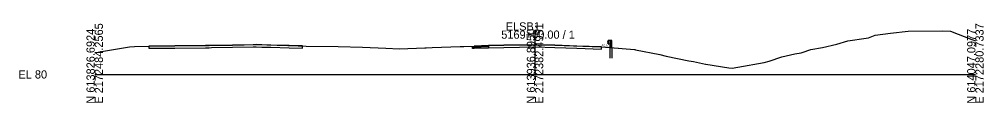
# Model space of a CAD drawing. Extents: x -26 to 1303, y -3010 to 12023.
# Drawn here: x -25.7 to 302.8, y -1509.7 to -1482.2 of the extents above; entities that cross this region are included whole.
import ezdxf

# ---------------------------------------------------------------- set-up
doc = ezdxf.new("R2010")
doc.units = 0
for name, color, linetype in [('RD_GPK_XS_Cell', 7, 'Continuous'), ('RD_PD_Final_TrvlWay', 7, 'Continuous'), ('RD_XS_Base', 7, 'Continuous'), ('RD_XS_ExGround', 7, 'Continuous'), ('RD_XS_ExPaveRet', 7, 'Continuous'), ('RD_XS_GR', 7, 'Continuous'), ('RD_XS_Pave', 7, 'Continuous'), ('RD_XS_PaveOvlay_CP', 7, 'Continuous'), ('RD_XS_TieSlope', 7, 'Continuous'), ('RD_XS_TX_ShdSlope', 7, 'Continuous')]:
    doc.layers.add(name, color=color, linetype=linetype)

msp = doc.modelspace()

# ---------------------------------------------------------------- linework, layer by layer
at = {"layer": 'RD_GPK_XS_Cell'}
for p, q in [((150, -1500), (150, -1485)), ((0, -1500), (150, -1500)), ((150, -1500), (300, -1500))]:
    msp.add_line(p, q, dxfattribs=at)
at = {"layer": 'RD_PD_Final_TrvlWay'}
for p, q in [((175.63, -1494.42), (175.63, -1490.81)), ((175.63, -1490.81), (176.13, -1490.85)), ((176.13, -1490.85), (176.13, -1494.42))]:
    msp.add_line(p, q, dxfattribs=at)
at = {"layer": 'RD_XS_Base'}
for p, q in [((128.72, -1491.15), (128.72, -1491.15)), ((128.72, -1491.15), (128.72, -1491.15)), ((128.73, -1490.65), (129.23, -1490.63)), ((128.73, -1491.15), (128.73, -1490.65)), ((128.73, -1490.65), (128.73, -1490.65)), ((129.22, -1491.13), (128.73, -1491.15)), ((134.17, -1490.98), (129.22, -1491.13)), ((129.22, -1491.13), (129.22, -1491.13)), ((129.23, -1490.63), (134.17, -1490.48)), ((129.23, -1490.63), (129.23, -1490.63)), ((134.17, -1490.92), (134.17, -1490.98))]:
    msp.add_line(p, q, dxfattribs=at)
at = {"layer": 'RD_XS_ExGround'}
msp.add_lwpolyline([(0, -1492.62), (2.34, -1492.18), (11.82, -1490.56), (13.51, -1490.5), (18.45, -1490.33), (27.33, -1490.24), (38.95, -1490.11), (46.94, -1489.98), (55.03, -1489.83), (69.32, -1490.23), (70.81, -1490.28), (72.02, -1490.3), (82.96, -1490.51), (91.27, -1490.74), (99.19, -1491.08), (103.8, -1491.27), (112.44, -1490.94), (112.57, -1490.94), (112.96, -1490.92), (114.94, -1490.85), (124.46, -1490.5), (125.78, -1490.45), (129.43, -1490.31), (132.16, -1490.23), (134.17, -1490.17), (139.37, -1490.06), (150.05, -1489.84), (156.78, -1490.05), (172.69, -1490.58), (183.85, -1491.49), (183.99, -1491.5), (184.26, -1491.55), (192.48, -1493.18), (194.68, -1493.74), (202.44, -1495.32), (203.99, -1495.55), (208.03, -1496.51), (208.15, -1496.54), (216.03, -1497.73), (217.17, -1497.89), (219.05, -1497.52), (228.03, -1495.91), (229.75, -1495.48), (234.11, -1494.02), (238.47, -1492.94), (240.61, -1492.62), (240.97, -1492.48), (243.96, -1491.45), (247.87, -1490.75), (252.86, -1489.61), (256.5, -1488.48), (262.79, -1487.57), (263.5, -1487.47), (263.6, -1487.45), (265.88, -1486.58), (271.12, -1485.85), (277.08, -1485.18), (288.97, -1485.15), (291.55, -1485.22), (298.8, -1488.07), (300, -1488.54)], dxfattribs=at)
at = {"layer": 'RD_XS_ExPaveRet'}
for p, q in [((37.7, -1490.13), (27.33, -1490.24)), ((38.95, -1490.11), (37.7, -1490.13)), ((39.81, -1490.1), (38.95, -1490.11)), ((55.03, -1489.83), (53.95, -1489.85)), ((60.02, -1489.97), (60, -1489.97)), ((172.68, -1490.58), (164.23, -1490.3)), ((172.69, -1490.58), (172.68, -1490.58))]:
    msp.add_line(p, q, dxfattribs=at)
for points in [[(60, -1489.97), (56.94, -1489.89), (55.03, -1489.83), (53.95, -1489.85), (46.94, -1489.98), (39.81, -1490.1), (38.95, -1490.11), (37.7, -1490.13), (27.33, -1490.24), (18.45, -1490.33), (18.45, -1490.33), (18.45, -1490.33), (18.45, -1490.33), (18.45, -1490.33), (18.45, -1490.33), (18.45, -1490.72), (18.45, -1491.08), (18.45, -1491.08), (18.45, -1491.08), (18.45, -1491.08), (18.45, -1491.08), (18.45, -1491.08), (27.33, -1490.99), (37.7, -1490.88), (38.95, -1490.86), (39.81, -1490.85), (46.94, -1490.73), (53.95, -1490.6), (55.03, -1490.58), (56.94, -1490.64), (60, -1490.72), (66.27, -1490.9), (70.81, -1491.03), (70.81, -1490.66), (70.81, -1490.28), (66.27, -1490.15), (60, -1489.97)], [(18.45, -1490.33), (18.45, -1490.72), (18.45, -1491.08), (18.45, -1491.08), (18.45, -1491.08), (18.45, -1491.08), (27.33, -1490.99), (37.7, -1490.88), (38.95, -1490.86), (39.81, -1490.85), (46.94, -1490.73), (53.95, -1490.6), (55.03, -1490.58), (56.94, -1490.64), (60, -1490.72), (66.27, -1490.9), (70.81, -1491.03), (70.81, -1490.66), (70.81, -1490.28), (66.27, -1490.15), (60.02, -1489.97)], [(27.33, -1490.24), (18.45, -1490.33), (18.45, -1490.33), (18.45, -1490.33), (18.45, -1490.33), (18.45, -1490.33)], [(53.95, -1489.85), (46.94, -1489.98), (39.81, -1490.1)], [(60, -1489.97), (56.94, -1489.89), (55.03, -1489.83)], [(172.69, -1490.58), (172.69, -1490.58), (172.69, -1490.58), (172.68, -1490.58), (164.23, -1490.3), (156.78, -1490.05), (150.07, -1489.85), (150.05, -1489.84), (150, -1489.85), (139.37, -1490.06), (134.17, -1490.17), (134.17, -1490.67), (134.17, -1490.92), (139.37, -1490.81), (150, -1490.6), (150.05, -1490.59), (150.07, -1490.6), (156.78, -1490.8), (164.23, -1491.05), (172.68, -1491.33), (172.69, -1491.33), (172.69, -1491.33), (172.69, -1491.33), (172.69, -1491.33), (172.69, -1491.08), (172.69, -1490.58), (172.69, -1490.58)], [(150.05, -1489.84), (150, -1489.85), (139.37, -1490.06), (139.37, -1490.06), (134.17, -1490.17)], [(134.17, -1490.17), (134.17, -1490.67), (134.17, -1490.92), (139.37, -1490.81), (150, -1490.6), (150.05, -1490.59), (150.07, -1490.6), (156.78, -1490.8), (164.23, -1491.05), (172.68, -1491.33), (172.69, -1491.33), (172.69, -1491.33), (172.69, -1491.33), (172.69, -1491.08), (172.69, -1490.58), (172.69, -1490.58), (172.69, -1490.58)], [(164.23, -1490.3), (156.78, -1490.05), (150.07, -1489.85), (150.05, -1489.84)]]:
    msp.add_lwpolyline(points, dxfattribs=at)
at = {"layer": 'RD_XS_GR'}
for p, q in [((174.69, -1488.71), (174.89, -1488.49)), ((174.76, -1488.78), (174.69, -1488.71)), ((174.69, -1489.29), (174.89, -1489.08)), ((174.76, -1489.37), (174.69, -1489.29)), ((174.96, -1489), (174.76, -1488.78)), ((174.96, -1489.58), (174.76, -1489.37)), ((174.89, -1488.49), (174.96, -1488.42)), ((174.89, -1489.08), (174.96, -1489)), ((174.96, -1488.42), (174.96, -1489.58)), ((175.63, -1488.42), (174.96, -1488.42)), ((174.96, -1488.42), (174.96, -1488.72)), ((174.96, -1488.72), (174.96, -1489.58)), ((174.96, -1489.58), (175.63, -1489.58)), ((175.63, -1488.42), (175.63, -1490.81)), ((175.88, -1488.42), (175.63, -1488.42)), ((175.63, -1489.58), (175.63, -1488.42)), ((175.63, -1490.81), (176.13, -1490.85)), ((176.13, -1488.42), (175.88, -1488.42)), ((176.13, -1490.85), (176.13, -1488.42))]:
    msp.add_line(p, q, dxfattribs=at)
at = {"layer": 'RD_XS_Pave'}
for p, q in [((134.17, -1490.17), (129.23, -1490.32)), ((129.23, -1490.32), (129.23, -1490.32)), ((129.23, -1490.32), (129.23, -1490.47)), ((134.17, -1490.33), (129.23, -1490.47)), ((129.23, -1490.47), (134.17, -1490.33)), ((129.23, -1490.47), (129.23, -1490.47)), ((129.23, -1490.47), (129.23, -1490.63)), ((129.23, -1490.47), (129.23, -1490.47)), ((129.23, -1490.47), (129.23, -1490.47)), ((129.23, -1490.63), (134.17, -1490.48)), ((129.23, -1490.63), (129.23, -1490.63)), ((129.23, -1490.63), (129.23, -1490.63))]:
    msp.add_line(p, q, dxfattribs=at)
at = {"layer": 'RD_XS_PaveOvlay_CP'}
for p in [(134.17, -1490.17), (129.23, -1490.32)]:
    msp.add_line(p, (129.23, -1490.32), dxfattribs=at)
at = {"layer": 'RD_XS_TieSlope'}
msp.add_line((172.69, -1490.58), (178.44, -1491.04), dxfattribs=at)

# ---------------------------------------------------------------- texts
at = {"layer": 'RD_GPK_XS_Cell'}
for s, p in [('N 613826.6924', (0, -1510)), ('E 2172484.2565', (2.8, -1510)), ('N 613936.8950', (150, -1510)), ('E 2172382.4951', (152.8, -1510)), ('N 614047.0977', (300, -1510)), ('E 2172280.7337', (302.8, -1510))]:
    msp.add_text(s, height=2.8, rotation=90, dxfattribs=at).set_placement(p)
for s, p in [('5169+00.00 / 1', (138.48, -1487.8)), ('ELSB1', (140, -1485)), ('EL 80', (-26, -1501.4))]:
    msp.add_text(s, height=2.8, dxfattribs=at).set_placement(p)
at = {"layer": 'RD_XS_TX_ShdSlope'}
msp.add_text('12.5:1', height=0.75, rotation=355.4261, dxfattribs=at).set_placement((172.65, -1490.29))

doc.saveas('drawing.dxf')
